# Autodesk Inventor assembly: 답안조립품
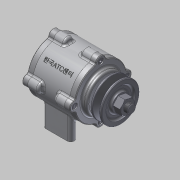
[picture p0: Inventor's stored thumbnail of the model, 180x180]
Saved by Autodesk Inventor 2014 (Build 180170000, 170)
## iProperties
Created: 2015-03
Part Number: 답안조립품
Document SubType Name: Assembly
Designer: MYHOME
Author: MYHOME
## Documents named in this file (11)
- C:\Documents and Settings\MYHOME\바탕 화면\450306V1007\답안조립품.iam
- C:\Documents and Settings\MYHOME\바탕 화면\450306V1007\본체.ipt
- C:\Documents and Settings\MYHOME\바탕 화면\450306V1007\커버2.ipt
- C:\Documents and Settings\MYHOME\바탕 화면\450306V1007\커버.ipt
- C:\Documents and Settings\MYHOME\바탕 화면\450306V1007\M 4 x 12.ipt
- C:\Documents and Settings\MYHOME\바탕 화면\450306V1007\오일실.ipt
- C:\Documents and Settings\MYHOME\바탕 화면\450306V1007\축.ipt
- C:\Documents and Settings\MYHOME\바탕 화면\450306V1007\키(4 x 4 x 12).ipt
- C:\Documents and Settings\MYHOME\바탕 화면\450306V1007\베어링 6204.ipt
- C:\Documents and Settings\MYHOME\바탕 화면\450306V1007\V벨트풀리.ipt
- C:\Documents and Settings\MYHOME\바탕 화면\450306V1007\너트 M12x1.25.ipt
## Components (14 placed, 6 different names)
1. KS B 2804 D D - 20 32 8:1
2. KS B 1311 (I) 4 x 4 x 12:1
3. KS B 2023 6204 - 20 x 47 x 14:1 — 각도:1
4. KS B 2023 6204 - 20 x 47 x 14:2 — 각도:2
5. 그루브 풀리1:1
6. KS B 1012 클래스 1 일반 - 미터 M12x1.25:1 — 각도:3
7. KS B 1003 - 미터 M 4 x 12:1
8. KS B 1003 - 미터 M 4 x 12:3
9. KS B 1003 - 미터 M 4 x 12:4
10. KS B 1003 - 미터 M 4 x 12:5
11. KS B 1003 - 미터 M 4 x 12:2
12. KS B 1003 - 미터 M 4 x 12:6
13. KS B 1003 - 미터 M 4 x 12:7
14. KS B 1003 - 미터 M 4 x 12:8
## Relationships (3: Angle 3)
- 각도:1 [Angle]: KS B 2023 6204 - 20 x 47 x 14:1
- 각도:2 [Angle]: KS B 2023 6204 - 20 x 47 x 14:2
- 각도:3 [Angle]: KS B 1012 클래스 1 일반 - 미터 M12x1.25:1
